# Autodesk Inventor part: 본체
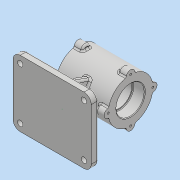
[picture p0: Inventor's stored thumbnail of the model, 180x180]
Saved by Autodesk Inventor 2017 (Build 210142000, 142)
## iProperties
Part Number: 본체
Material: 일반
Document SubType Name: Modeling
Designer: MRC
Density: 1 g/cm^3
Appearance: 기본값
Author: MRC
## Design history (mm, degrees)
sketch "스케치1"
  geometry: L1 (-43.5, 0)-(43.5, 0); L2 (-43.5, 23.5)-(-24.5, 23.5); L3 (-24.5, 23.5)-(-24.5, 21); L4 (-24.5, 21)-(24.5, 21); L5 (24.5, 21)-(24.5, 23.5); L6 (24.5, 23.5)-(43.5, 23.5); L7 (43.5, 23.5)-(43.5, 37); L8 (43.5, 37)-(-43.5, 37); L9 (-43.5, 37)-(-43.5, 23.5); 2 further points
  constraints: 18 end point, 5 perpendicular, 4 point on line, 2 horizontal, 1 coincident, 1 midpoint, 1 vertical
  dimensions: "d0" = 87 distance of L1.start L1.end; "d1" = 42 diameter of L4 L1; "d2" = 47 diameter of L6 L1; "d3" = 74 diameter of L8 L1; "d4" = 19 distance between parallel lines of L3 L9; "d5" = 19 distance between parallel lines of L7 L5
revolve "회전1" sketch "스케치1" stored, may be unused: angle "d6" = 90 deg
fillet "모깎기1" dims "d7" = 1
chamfer "모따기1" distance "d8" = 1; stored, may be unused: second distance "d9" = 2, angle "d10" = 45 deg
chamfer "모따기2" distance "d11" = 1; stored, may be unused: second distance "d12" = 2, angle "d13" = 45 deg
sketch "스케치2"
  geometry: A1 r 7 centre (0, 37) between (6.969, 36.338) and (-6.969, 36.338); A2 r 37 centre (0, 0) between (0, 37) and (-6.969, 36.338) reference; 1 further point
  constraints: 5 point on circle, 1 centre point, 1 vertical alignment
  dimensions: "d14" = 14 diameter of A1
extrude "돌출1" join sketch "스케치2" distance "d15" = 14; taper "d16" = 0 deg
hole "구멍1" diameter "d19" = 3.242; stored, may be unused: countersink angle "d23" = 90 deg, drill point angle "d25" = 118 deg; dims "d17" = 10, "d18" = 10, "d20" = 8, "d21" = 4, "d22" = 2, "d24" = 10
fillet "모깎기2" dims "d29" = 3
fillet "모깎기3" dims "d30" = 3
sketch "스케치3"
  geometry: L1 (-70, -70)-(60, -70); L2 (60, -70)-(60, -82); L3 (60, -82)-(-70, -82); L4 (-70, -82)-(-70, -70); 1 further point
  constraints: 8 end point, 2 parallel, 1 horizontal, 1 perpendicular
  dimensions: "d31" = 12 distance of L1.end L2.end; "d32" = 130 distance of L2.end L3.end; "d33" = 82 distance from line of point (0, 0) L3; "d64" = 70 distance from line of point (0, 0) L4
extrude "돌출2" join sketch "스케치3" stored distance "d34" = 110; taper "d35" = 0 deg
fillet "모깎기4" dims "d36" = 12
sketch "스케치4"
  geometry: C1 r 4.5 at (0, 98); C2 r 4.5 at (106, 98); C3 r 4.5 at (106, 12); C4 r 4.5 at (0, 12); A1 r 12 centre (106, 98) between (118, 98) and (106, 110) reference; A2 r 12 centre (0, 98) between (0, 110) and (-12, 98) reference; A3 r 12 centre (0, 12) between (-12, 12) and (0, 0) reference; A4 r 12 centre (106, 12) between (106, 0) and (118, 12) reference; 1 further point
  constraints: 4 centre point, 4 concentric, 3 equal radius
  dimensions: "d37" = 9 diameter of C1
extrude "돌출3" cut sketch "스케치4" stored distance "d38" = 110; taper "d39" = 0 deg
fillet "모깎기5" dims "d40" = 3
sketch "스케치5"
  geometry: L1 (53, 57)-(63, 57); L2 (63, 57)-(63, 47); L3 (63, 47)-(53, 47); L4 (53, 47)-(53, 57); 3 further points
  constraints: 8 end point, 2 midpoint, 2 parallel, 1 horizontal, 1 horizontal alignment, 1 perpendicular, 1 vertical alignment
  dimensions: "d41" = 10 distance of L1.start L1.end; "d42" = 10 distance of L1.end L2.end
extrude "돌출4" join sketch "스케치5" stored distance "d43" = 110; taper "d44" = 0 deg
sketch "스케치6"
  geometry: L1 (30, -70)-(19.725, -41.769); L2 (-58, -70)-(48, -70) reference; 1 further point
  constraints: 2 end point, 1 point on line
  dimensions: "d45" = 110 deg angle of L2 L1; "d46" = 30 horizontal distance of L1.start point (0, 0)
feature "리브1" sketch "스케치6" dims "d47" = 1, "d48" = 10, "d49" = 0, "d50" = 0, "d51" = 1, "d52" = 1
sketch "스케치7"
  geometry: L1 (-44.465, -31.706)-(-70, -41); L2 (-70, 43)-(-70, -43) reference; L3 (-73, -55)-(-82, -55) reference; 1 further point
  constraints: 2 end point, 1 point on line
  dimensions: "d53" = 110 deg angle of L2 L1; "d54" = 14 distance from line of L3 L1.end
feature "리브2" sketch "스케치7" dims "d55" = 1, "d56" = 10, "d57" = 0, "d58" = 0, "d59" = 1, "d60" = 1
fillet "모깎기6" dims "d61" = 3
fillet "모깎기7" dims "d62" = 3
sketch "스케치8"
  geometry: 2 further points
  constraints: 1 horizontal alignment, 1 other
  dimensions: "d63" = 58 distance of point (58, -52) point (0, -52)
feature "엠보싱1" sketch "스케치8" dims "d0" = 87, "d1" = 42, "d2" = 47, "d3" = 74, "d4" = 19, "d5" = 19, "d65" = 0.5, "d66" = 0
sketch "스케치9"
  geometry: 1 further point
node "솔리드1"
pattern_circular "원형 패턴1" dims angle "d27" = 360 deg
mirror "미러1"
mirror "미러2"
mirror "미러3"
